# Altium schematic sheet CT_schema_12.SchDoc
size 387 x 278 mm
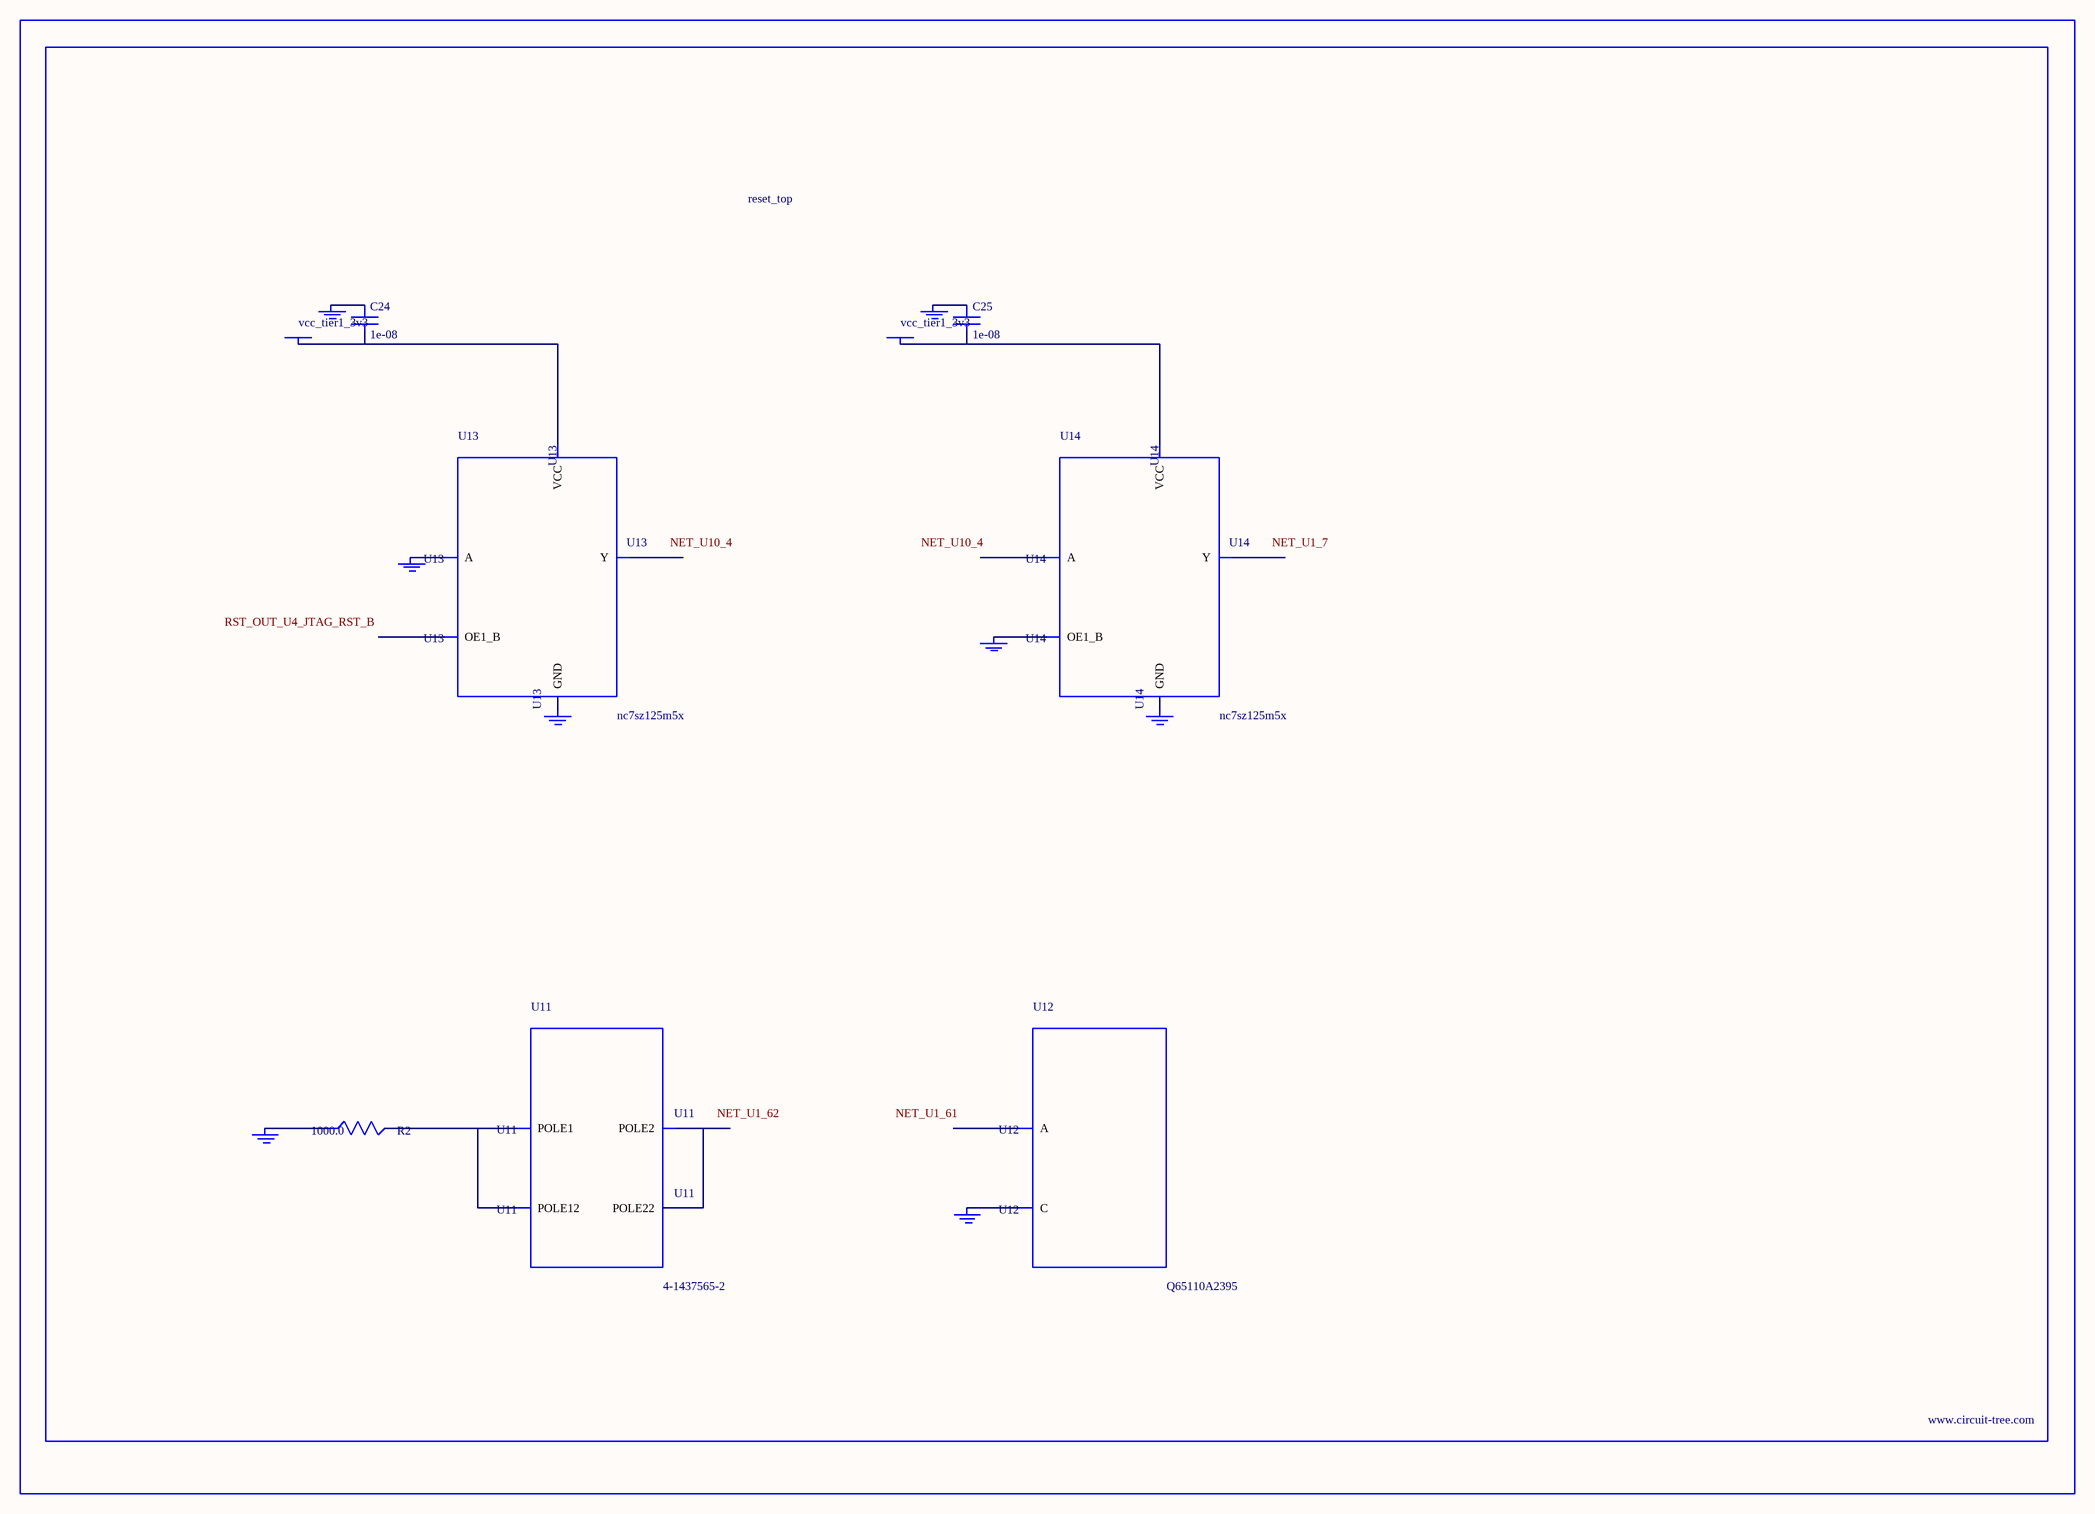
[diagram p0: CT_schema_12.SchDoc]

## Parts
BORDER11  (no value)
C24  1e-08  [C0402]
C25  1e-08  [C0402]
GND_INSTANCE_11_0  (no value)
GND_INSTANCE_11_1  (no value)
GND_INSTANCE_11_2  (no value)
GND_INSTANCE_11_3  (no value)
GND_INSTANCE_11_4  (no value)
GND_INSTANCE_11_5  (no value)
GND_INSTANCE_11_6  (no value)
GND_INSTANCE_11_7  (no value)
POWER_INSTANCE_11_0  vcc_tier1_3v3
POWER_INSTANCE_11_1  vcc_tier1_3v3
R2  1000.0  [R0603]
U11  4-1437565-2  [SW_4-1437565-2]
U12  Q65110A2395  [LGM67K-G1J2-24-Z]
U13  nc7sz125m5x  [NC7SZ125M5X]
U14  nc7sz125m5x  [NC7SZ125M5X]

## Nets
NetC24_1: C24.1 GND_INSTANCE_11_2.0(GND)
NetC24_2: C24.2 POWER_INSTANCE_11_0.0(PWR) U13.5(VCC)
NetC25_1: C25.1 GND_INSTANCE_11_5.0(GND)
NetC25_2: C25.2 POWER_INSTANCE_11_1.0(PWR) U14.5(VCC)
NetGND_INSTANCE_11_0_0: GND_INSTANCE_11_0.0(GND) R2.1
NetGND_INSTANCE_11_1_0: GND_INSTANCE_11_1.0(GND) U12.C
NetGND_INSTANCE_11_3_0: GND_INSTANCE_11_3.0(GND) U13.2(A)
NetGND_INSTANCE_11_4_0: GND_INSTANCE_11_4.0(GND) U13.3(GND)
NetGND_INSTANCE_11_6_0: GND_INSTANCE_11_6.0(GND) U14.1(OE1_B)
NetGND_INSTANCE_11_7_0: GND_INSTANCE_11_7.0(GND) U14.3(GND)
NetR2_2: R2.2 U11.1(POLE1) U11.2(POLE12)
NetU11_3: U11.3(POLE2) U11.4(POLE22)

Not connected (* = marked no-connect by the designer): U12 A; U13 1(OE1_B) 4(Y); U14 2(A) 4(Y)

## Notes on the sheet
- Labels drawn without touching a wire or pin: NET_U1_7, NET_U1_61, NET_U1_62, NET_U10_4, RST_OUT_U4_JTAG_RST_B

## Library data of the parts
BORDER11 = BORDER_PAGE11
C24 C25 = C0402C103K3RAC
GND_INSTANCE_11_0-GND_INSTANCE_11_7 = GND
POWER_INSTANCE_11_0 POWER_INSTANCE_11_1 = PWR
R2 = RC0603JR-071KL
